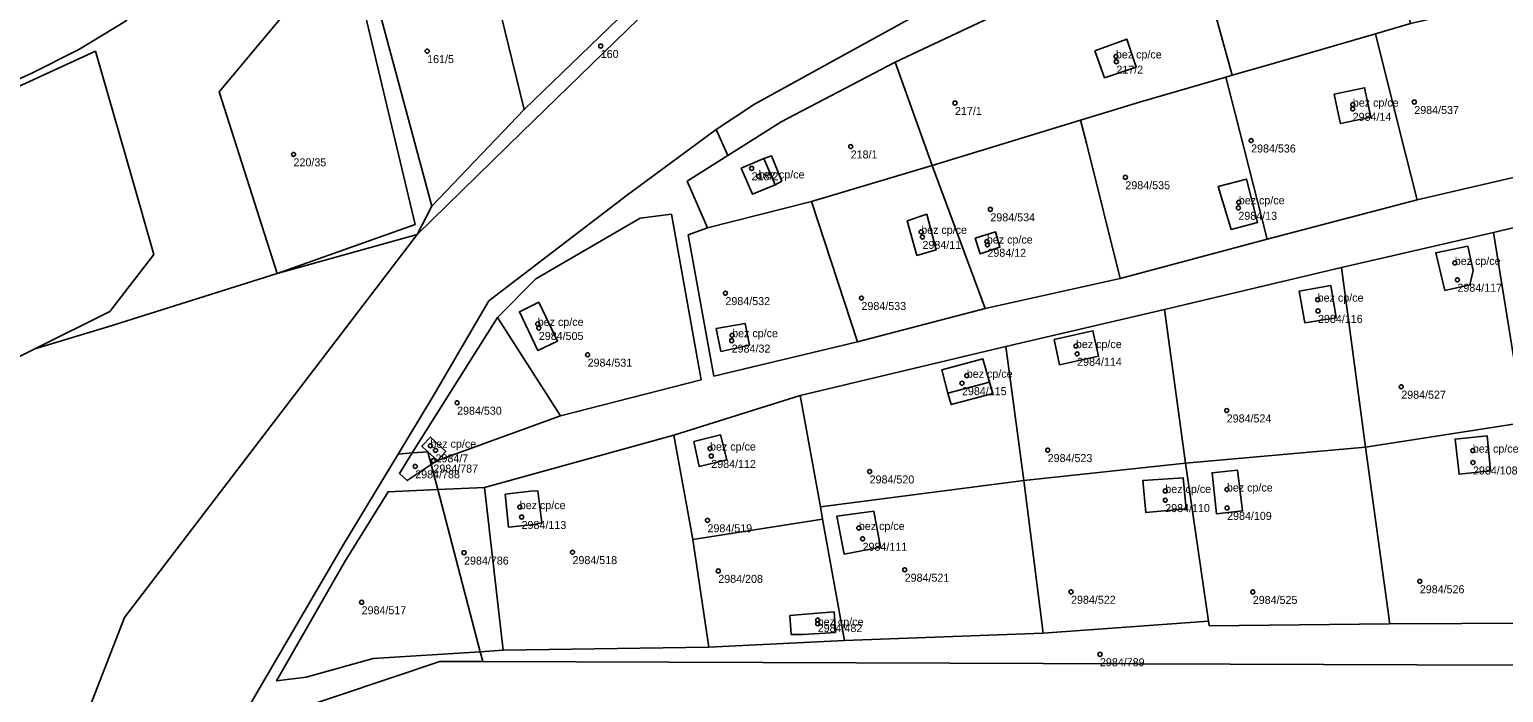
# Model space of a CAD drawing. Extents: x -878211 to -870363, y -1058464 to -1052522.
# Drawn here: x -874051.4 to -873867.2, y -1056092.9 to -1056010.1 of the extents above; entities that cross this region are included whole.
import ezdxf

# ---------------------------------------------------------------- set-up
doc = ezdxf.new("R2010")
doc.units = 0
for name, color, linetype in [('Vrstva 50', 7, 'Continuous'), ('Vrstva 51', 7, 'Continuous'), ('Vrstva 52', 7, 'Continuous')]:
    doc.layers.add(name, color=color, linetype=linetype)

msp = doc.modelspace()

# ---------------------------------------------------------------- linework, layer by layer
at = {"layer": 'Vrstva 50'}
for centre in [(-873980.05, -1056012.16994), (-874001.74, -1056012.80994), (-873915.68, -1056013.46994), (-873915.62, -1056014.12994), (-873935.78, -1056019.28994), (-873886.07, -1056019.48994), (-873878.39, -1056019.16994), (-873886.09, -1056020.01994), (-873948.82, -1056024.72994), (-873898.78, -1056023.97994), (-874018.44, -1056025.70994), (-873961.2, -1056027.44994), (-873960.31, -1056028.45994), (-873914.49, -1056028.56994), (-873900.37, -1056032.38994), (-873900.32, -1056031.68994), (-873931.36, -1056032.57994), (-873940.01, -1056035.38994), (-873939.85, -1056036.02994), (-873931.8, -1056036.59994), (-873931.73, -1056037.00994), (-873873.33, -1056039.26994), (-873873, -1056041.37994), (-873964.47, -1056043.04994), (-873947.47, -1056043.65994), (-873890.46, -1056043.85994), (-873890.42, -1056045.26994), (-873987.92, -1056046.88994), (-873987.79, -1056047.39994), (-873963.69, -1056048.97994), (-873963.63, -1056048.29994), (-873981.69, -1056050.73994), (-873920.68, -1056049.65994), (-873920.52, -1056050.62994), (-873934.91, -1056054.29994), (-873934.31, -1056053.35994), (-873880.02, -1056054.73994), (-873998, -1056056.73994), (-873901.83, -1056057.70994), (-874001.34, -1056062.10994), (-874000.7, -1056062.68994), (-873966.39, -1056062.45994), (-873966.24, -1056063.38994), (-873924.2, -1056062.65994), (-873871.08, -1056062.71994), (-874003.23, -1056064.68994), (-874000.96, -1056063.96994), (-873946.45, -1056065.32994), (-873871.06, -1056064.20994), (-873909.51, -1056068.90994), (-873909.5, -1056067.75994), (-873901.81, -1056067.57994), (-873990.17, -1056069.77994), (-873989.94, -1056071.01994), (-873901.78, -1056069.87994), (-873966.71, -1056071.42994), (-873947.8, -1056072.38994), (-873947.33, -1056073.73994), (-873997.13, -1056075.46994), (-873983.58, -1056075.40994), (-873965.36, -1056077.74994), (-873942.07, -1056077.60994), (-873921.28, -1056080.35994), (-873898.57, -1056080.37994), (-873877.7, -1056079.04994), (-874009.93, -1056081.66994), (-873952.94, -1056083.89994), (-873952.94, -1056084.34994), (-873917.67, -1056088.16994)]:
    msp.add_circle(centre, 0.25, dxfattribs=at)
at = {"layer": 'Vrstva 51'}
for points in [[(-874061.78, -1056020.31), (-874051.21, -1056015.58), (-874045.28, -1056012.6), (-874039.36, -1056009.01), (-874029.28, -1055999.36), (-874026.64, -1055995.1), (-874024.59, -1055990.32), (-874024.07, -1055987.79), (-874023.46, -1055978.22), (-874024.41, -1055972.01), (-874026.04, -1055967.55), (-874027.4, -1055965.3), (-874028.36, -1055963.96), (-874031.92, -1055959.69), (-874036.44, -1055955.98), (-874044.57, -1055950.98), (-874047.99, -1055949.47), (-874050.57, -1055948.5), (-874079.9, -1055941.21)], [(-873865.37, -1055954.75), (-873878.23, -1055960.39), (-873892.52, -1055966.18), (-873911.31, -1055974.31), (-873925.46, -1055980.46), (-873932.28, -1055983.42), (-873939.2, -1055986.41), (-873946.14, -1055989.65), (-873958.05, -1055994.81), (-873966.71, -1056000.36), (-873975.38, -1056008.83), (-873989.92, -1056022.91), (-874003.01, -1056035.73), (-874039.57, -1056083.57), (-874048.77, -1056107.25), (-874057.99, -1056135.83), (-874062.23, -1056148.73), (-874064.44, -1056172.46), (-874059.65, -1056228.47), (-874059.11, -1056233.23), (-874058.08, -1056239.54)], [(-874040.92, -1056237.64), (-874034.08, -1056235.73), (-874035.3, -1056231.92), (-874038.77, -1056221.03), (-874041.72, -1056201.74), (-874042.62, -1056175.62), (-874041.38, -1056163.05), (-874040.39, -1056153.05), (-874039.88, -1056147.87), (-874035.94, -1056133.05), (-874033.12, -1056122.42), (-874026.65, -1056099.18), (-874012.21, -1056074.45), (-874005.36, -1056063.14), (-874001, -1056055.93), (-873994.02, -1056044.02), (-873976.69, -1056030.75), (-873965.62, -1056022.6), (-873960.85, -1056019.45), (-873933.34, -1056004.26), (-873896.15, -1055987.86), (-873830.39, -1055958.21)], [(-873830.39, -1055958.21), (-873896.15, -1055987.86), (-873933.34, -1056004.26), (-873960.85, -1056019.45), (-873965.62, -1056022.6), (-873964.15, -1056025.83), (-873957.5, -1056021.62), (-873943.25, -1056014.2), (-873906.38, -1055996.82), (-873884.55, -1055987.56), (-873872.55, -1055982.17), (-873859.95, -1055976.8)], [(-874061.28, -1056021.1), (-874043.19, -1056012.81), (-874038.62, -1056028.71), (-874035.88, -1056038.23), (-874041.39, -1056045.32), (-874050.77, -1056050.02), (-874041.66, -1056047.24), (-874020.49, -1056040.6), (-874003.01, -1056035.73), (-874001.15, -1056032.18), (-874010.89, -1055995.93)], [(-874039.36, -1056009.01), (-874045.28, -1056012.6), (-874051.21, -1056015.58), (-874061.78, -1056020.31)], [(-873859.93, -1056027.19), (-873878.04, -1056031.39), (-873896.77, -1056036.31), (-873915.14, -1056041.21), (-873932.03, -1056044.96), (-873947.96, -1056049.12), (-873965.9, -1056053.41), (-873969.12, -1056035.77), (-873966.69, -1056034.9), (-873969.26, -1056029.06), (-873964.15, -1056025.83), (-873965.62, -1056022.6), (-873976.69, -1056030.75), (-873994.02, -1056044.02), (-874001, -1056055.93), (-874005.36, -1056063.14), (-874003.6, -1056063), (-873992.97, -1056046.1), (-873988.15, -1056041.27), (-873975.13, -1056033.66), (-873971.22, -1056033.18), (-873967.5, -1056053.87), (-873985.07, -1056058.37), (-874000.43, -1056063.95), (-874001.22, -1056064.47), (-874000.4, -1056067.59), (-873994.59, -1056067.33), (-873970.91, -1056060.77), (-873955.12, -1056055.84), (-873929.41, -1056049.7), (-873909.62, -1056045.07), (-873887.49, -1056039.84), (-873868.5, -1056035.48), (-873846.23, -1056030.16)], [(-873840.34, -1056089.55), (-873878.08, -1056089.5), (-873994.8, -1056089.08), (-874000.16, -1056089.06), (-874019.41, -1056095.51), (-874027.71, -1056108.65), (-874034.52, -1056132.5), (-874040.39, -1056153.05), (-874041.38, -1056163.05), (-874040.47, -1056163.31), (-874027.4, -1056124.02), (-874022.95, -1056110.18), (-874014.9, -1056098.66), (-874004.66, -1056094.51), (-873961.82, -1056094.39), (-873878.1, -1056095.5), (-873849.14, -1056094.93)]]:
    msp.add_lwpolyline(points, dxfattribs=at)
for points in [[(-873971.94, -1056003.04), (-873976.33, -1055986.86), (-873996.44, -1055992.14), (-873989.6, -1056020.11)], [(-873884.55, -1055987.56), (-873906.38, -1055996.82), (-873903.56, -1056007.06), (-873901.15, -1056015.82), (-873896.45, -1056014.46), (-873883.25, -1056010.63), (-873878.85, -1056009.35), (-873879.27, -1056007.63), (-873881.39, -1055998.99)], [(-873996.44, -1055992.14), (-874010.89, -1055995.93), (-874001.15, -1056032.18), (-873989.6, -1056020.11)], [(-873901.15, -1056015.82), (-873903.56, -1056007.06), (-873906.38, -1055996.82), (-873943.25, -1056014.2), (-873938.62, -1056027.09), (-873920.09, -1056021.43), (-873912.71, -1056019.18), (-873901.93, -1056016.05)], [(-874003.26, -1056034.48), (-874011.74, -1055998.72), (-874027.74, -1056017.87), (-874020.49, -1056040.6)], [(-874003.26, -1056034.48), (-874020.49, -1056040.6), (-874027.74, -1056017.87), (-874011.74, -1055998.72)], [(-873975.38, -1056008.83), (-873966.71, -1056000.36), (-873971.94, -1056003.04), (-873989.6, -1056020.11), (-874001.15, -1056032.18), (-874003.01, -1056035.73), (-873989.92, -1056022.91)], [(-873883.25, -1056010.63), (-873880.23, -1056022.67), (-873878.04, -1056031.39), (-873859.93, -1056027.19), (-873863.92, -1056005.93), (-873878.85, -1056009.35)], [(-873917.1, -1056016.13), (-873918.3, -1056012.77), (-873914.33, -1056011.3), (-873913.16, -1056014.81)], [(-873917.1, -1056016.13), (-873913.16, -1056014.81), (-873914.33, -1056011.3), (-873918.3, -1056012.77)], [(-873880.23, -1056022.67), (-873883.25, -1056010.63), (-873896.45, -1056014.46), (-873901.15, -1056015.82), (-873901.93, -1056016.05), (-873900.77, -1056020.61), (-873896.77, -1056036.31), (-873878.04, -1056031.39)], [(-874068.51, -1056024.22), (-874079.34, -1056028.88), (-874068.35, -1056058.84), (-874050.77, -1056050.02), (-874041.39, -1056045.32), (-874035.88, -1056038.23), (-874038.62, -1056028.71), (-874043.19, -1056012.81), (-874061.28, -1056021.1)], [(-873938.62, -1056027.09), (-873943.25, -1056014.2), (-873957.5, -1056021.62), (-873964.15, -1056025.83), (-873969.26, -1056029.06), (-873966.69, -1056034.9), (-873953.71, -1056031.61)], [(-873896.77, -1056036.31), (-873900.77, -1056020.61), (-873901.93, -1056016.05), (-873912.71, -1056019.18), (-873920.09, -1056021.43), (-873919.37, -1056024.32), (-873915.14, -1056041.21)], [(-873887.86, -1056020.78), (-873887.63, -1056021.85), (-873883.84, -1056021.06), (-873884.6, -1056017.39), (-873888.4, -1056018.2)], [(-873887.86, -1056020.78), (-873888.4, -1056018.2), (-873884.6, -1056017.39), (-873883.84, -1056021.06), (-873887.63, -1056021.85)], [(-873919.37, -1056024.32), (-873920.09, -1056021.43), (-873938.62, -1056027.09), (-873932.03, -1056044.96), (-873915.14, -1056041.21)], [(-873957.42, -1056029.06), (-873958.25, -1056029.51), (-873961.09, -1056030.69), (-873962.49, -1056027.44), (-873959.66, -1056026.22), (-873958.72, -1056025.88)], [(-873957.42, -1056029.06), (-873958.72, -1056025.88), (-873959.66, -1056026.22), (-873962.49, -1056027.44), (-873961.09, -1056030.69), (-873958.25, -1056029.51)], [(-873932.03, -1056044.96), (-873938.62, -1056027.09), (-873953.71, -1056031.61), (-873947.96, -1056049.12)], [(-873897.97, -1056034.22), (-873899.37, -1056028.79), (-873902.88, -1056029.7), (-873901.27, -1056035.08)], [(-873897.97, -1056034.22), (-873901.27, -1056035.08), (-873902.88, -1056029.7), (-873899.37, -1056028.79)], [(-873861.04, -1056058.94), (-873842.65, -1056057.61), (-873846.23, -1056030.16), (-873868.5, -1056035.48), (-873864.66, -1056059.2)], [(-873953.71, -1056031.61), (-873966.69, -1056034.9), (-873969.12, -1056035.77), (-873965.9, -1056053.41), (-873947.96, -1056049.12)], [(-873985.07, -1056058.37), (-873967.5, -1056053.87), (-873971.22, -1056033.18), (-873975.13, -1056033.66), (-873988.15, -1056041.27), (-873992.97, -1056046.1)], [(-873938.15, -1056037.61), (-873939.31, -1056033.18), (-873941.74, -1056033.99), (-873940.55, -1056038.33)], [(-873938.15, -1056037.61), (-873940.55, -1056038.33), (-873941.74, -1056033.99), (-873939.31, -1056033.18)], [(-874083.99, -1056066.24), (-874080.7, -1056077.88), (-874075.33, -1056096.89), (-874092.05, -1056109.34), (-874118.47, -1056117.14), (-874116.81, -1056122.76), (-874101.89, -1056134.11), (-874098.83, -1056136.48), (-874062.01, -1056135.86), (-874057.99, -1056135.83), (-874048.77, -1056107.25), (-874039.57, -1056083.57), (-874003.01, -1056035.73), (-874020.49, -1056040.6), (-874041.66, -1056047.24), (-874050.77, -1056050.02), (-874068.35, -1056058.84)], [(-873933.26, -1056036.18), (-873932.65, -1056038.12), (-873930.16, -1056037.29), (-873930.73, -1056035.39)], [(-873933.26, -1056036.18), (-873930.73, -1056035.39), (-873930.16, -1056037.29), (-873932.65, -1056038.12)], [(-873868.5, -1056035.48), (-873887.49, -1056039.84), (-873884.49, -1056062.27), (-873864.66, -1056059.2)], [(-873871.46, -1056042), (-873871.04, -1056040.2), (-873871.7, -1056037.17), (-873875.71, -1056038), (-873874.56, -1056042.71)], [(-873871.46, -1056042), (-873874.56, -1056042.71), (-873875.71, -1056038), (-873871.7, -1056037.17), (-873871.04, -1056040.2)], [(-873907, -1056064.3), (-873884.49, -1056062.27), (-873887.49, -1056039.84), (-873909.62, -1056045.07)], [(-873888.82, -1056042.1), (-873892.79, -1056042.8), (-873892.05, -1056046.75), (-873888.14, -1056046.12)], [(-873888.82, -1056042.1), (-873888.14, -1056046.12), (-873892.05, -1056046.75), (-873892.79, -1056042.8)], [(-873987.79, -1056044.18), (-873990.21, -1056045.38), (-873987.9, -1056050.21), (-873985.45, -1056049.03)], [(-873987.79, -1056044.18), (-873985.45, -1056049.03), (-873987.9, -1056050.21), (-873990.21, -1056045.38)], [(-873909.62, -1056045.07), (-873929.41, -1056049.7), (-873927.19, -1056066.46), (-873907, -1056064.3)], [(-874003.6, -1056063), (-874001.64, -1056062.85), (-874002.41, -1056062.16), (-874001.33, -1056061.02), (-873999.41, -1056062.83), (-874000.43, -1056063.95), (-873985.07, -1056058.37), (-873992.97, -1056046.1)], [(-873965.63, -1056047.46), (-873965.03, -1056050.32), (-873961.45, -1056049.53), (-873962.02, -1056046.82)], [(-873965.63, -1056047.46), (-873962.02, -1056046.82), (-873961.45, -1056049.53), (-873965.03, -1056050.32)], [(-873918.55, -1056047.75), (-873923.41, -1056048.85), (-873922.72, -1056051.99), (-873917.84, -1056050.9)], [(-873918.55, -1056047.75), (-873917.84, -1056050.9), (-873922.72, -1056051.99), (-873923.41, -1056048.85)], [(-873927.19, -1056066.46), (-873929.41, -1056049.7), (-873955.12, -1056055.84), (-873952.61, -1056069.75)], [(-873937.44, -1056052.61), (-873936.66, -1056055.54), (-873936.26, -1056056.97), (-873931.06, -1056055.59), (-873931.47, -1056054.18), (-873932.29, -1056051.25)], [(-873937.44, -1056052.61), (-873932.29, -1056051.25), (-873931.47, -1056054.18), (-873931.06, -1056055.59), (-873936.26, -1056056.97), (-873936.66, -1056055.54)], [(-873955.12, -1056055.84), (-873970.91, -1056060.77), (-873968.55, -1056073.84), (-873952.33, -1056071.3), (-873952.61, -1056069.75)], [(-873863.42, -1056084.29), (-873863.45, -1056083.69), (-873864.66, -1056059.2), (-873884.49, -1056062.27), (-873881.55, -1056083.76), (-873881.47, -1056084.35)], [(-873999.41, -1056062.83), (-874001.33, -1056061.02), (-874002.41, -1056062.16), (-874001.64, -1056062.85), (-874000.43, -1056063.95)], [(-873992.23, -1056087.66), (-873966.56, -1056087.27), (-873968.55, -1056073.84), (-873970.91, -1056060.77), (-873994.59, -1056067.33)], [(-873967.75, -1056064.71), (-873964.3, -1056063.86), (-873965.07, -1056060.76), (-873968.4, -1056061.59)], [(-873967.75, -1056064.71), (-873968.4, -1056061.59), (-873965.07, -1056060.76), (-873964.3, -1056063.86)], [(-873868.87, -1056065.26), (-873869.28, -1056060.88), (-873873.3, -1056061.27), (-873872.79, -1056065.66)], [(-873868.87, -1056065.26), (-873872.79, -1056065.66), (-873873.3, -1056061.27), (-873869.28, -1056060.88)], [(-874012.08, -1056076.67), (-874006.62, -1056067.86), (-874000.4, -1056067.59), (-874001.22, -1056064.47), (-874004.25, -1056066.47), (-874005.21, -1056065.57), (-874003.6, -1056063), (-874005.36, -1056063.14), (-874012.21, -1056074.45), (-874026.65, -1056099.18), (-874033.12, -1056122.42), (-874035.94, -1056133.05), (-874034.52, -1056132.5), (-874027.71, -1056108.65), (-874019.41, -1056095.51), (-874000.16, -1056089.06), (-873994.8, -1056089.08), (-873995.12, -1056087.84), (-874008.5, -1056088.69), (-874016.88, -1056091.03), (-874020.55, -1056091.49)], [(-874001.22, -1056064.47), (-874001.64, -1056062.85), (-874003.6, -1056063), (-874005.21, -1056065.57), (-874004.25, -1056066.47)], [(-874001.22, -1056064.47), (-874000.43, -1056063.95), (-874001.64, -1056062.85)], [(-873881.55, -1056083.76), (-873884.49, -1056062.27), (-873907, -1056064.3), (-873904.11, -1056084.01), (-873904.02, -1056084.6), (-873881.47, -1056084.35)], [(-873907, -1056064.3), (-873927.19, -1056066.46), (-873924.77, -1056085.52), (-873904.11, -1056084.01)], [(-873903.09, -1056070.63), (-873899.87, -1056070.25), (-873900.5, -1056065.14), (-873903.66, -1056065.49)], [(-873903.09, -1056070.63), (-873903.66, -1056065.49), (-873900.5, -1056065.14), (-873899.87, -1056070.25)], [(-873949.6, -1056086.44), (-873924.77, -1056085.52), (-873927.19, -1056066.46), (-873952.61, -1056069.75), (-873952.33, -1056071.3)], [(-873906.88, -1056069.99), (-873907.28, -1056066.1), (-873912.3, -1056066.44), (-873911.93, -1056070.45)], [(-873906.88, -1056069.99), (-873911.93, -1056070.45), (-873912.3, -1056066.44), (-873907.28, -1056066.1)], [(-874000.4, -1056067.59), (-874006.62, -1056067.86), (-874012.08, -1056076.67), (-874020.55, -1056091.49), (-874016.88, -1056091.03), (-874008.5, -1056088.69), (-873995.12, -1056087.84)], [(-873992.23, -1056087.66), (-873994.59, -1056067.33), (-874000.4, -1056067.59), (-873995.12, -1056087.84)], [(-873988.36, -1056071.96), (-873987.41, -1056071.73), (-873987.92, -1056067.76), (-873988.84, -1056067.77), (-873991.98, -1056068.16), (-873991.56, -1056072.29)], [(-873988.36, -1056071.96), (-873991.56, -1056072.29), (-873991.98, -1056068.16), (-873988.84, -1056067.77), (-873987.92, -1056067.76), (-873987.41, -1056071.73)], [(-873945.92, -1056070.3), (-873950.54, -1056070.92), (-873949.65, -1056075.65), (-873945.08, -1056074.79)], [(-873945.92, -1056070.3), (-873945.08, -1056074.79), (-873949.65, -1056075.65), (-873950.54, -1056070.92)], [(-873952.33, -1056071.3), (-873968.55, -1056073.84), (-873966.56, -1056087.27), (-873949.6, -1056086.44)], [(-873994.8, -1056089.08), (-873878.08, -1056089.5), (-873840.34, -1056089.55), (-873842.5, -1056082.5), (-873863.42, -1056084.29), (-873881.47, -1056084.35), (-873904.02, -1056084.6), (-873904.11, -1056084.01), (-873924.77, -1056085.52), (-873949.6, -1056086.44), (-873966.56, -1056087.27), (-873992.23, -1056087.66), (-873995.12, -1056087.84)], [(-873950.73, -1056085.43), (-873954.74, -1056085.68), (-873956.24, -1056085.71), (-873956.44, -1056083.32), (-873954.97, -1056083.2), (-873950.89, -1056082.86)], [(-873950.73, -1056085.43), (-873950.89, -1056082.86), (-873954.97, -1056083.2), (-873956.44, -1056083.32), (-873956.24, -1056085.71), (-873954.74, -1056085.68)]]:
    msp.add_lwpolyline(points, close=True, dxfattribs=at)
at = {"layer": 'Vrstva 52'}
for points in [[(-873918.3, -1056012.77), (-873917.1, -1056016.13), (-873913.16, -1056014.81), (-873914.33, -1056011.3)], [(-873887.63, -1056021.85), (-873883.84, -1056021.06), (-873884.6, -1056017.39), (-873888.4, -1056018.2), (-873887.86, -1056020.78)], [(-873962.49, -1056027.44), (-873961.09, -1056030.69), (-873958.25, -1056029.51), (-873959.66, -1056026.22)], [(-873899.37, -1056028.79), (-873902.88, -1056029.7), (-873901.27, -1056035.08), (-873897.97, -1056034.22)], [(-873939.31, -1056033.18), (-873941.74, -1056033.99), (-873940.55, -1056038.33), (-873938.15, -1056037.61)], [(-873933.26, -1056036.18), (-873932.65, -1056038.12), (-873930.16, -1056037.29), (-873930.73, -1056035.39)], [(-873871.7, -1056037.17), (-873875.71, -1056038), (-873874.56, -1056042.71), (-873871.46, -1056042), (-873871.04, -1056040.2)], [(-873892.79, -1056042.8), (-873892.05, -1056046.75), (-873888.14, -1056046.12), (-873888.82, -1056042.1)], [(-873990.21, -1056045.38), (-873987.9, -1056050.21), (-873985.45, -1056049.03), (-873987.79, -1056044.18)], [(-873965.63, -1056047.46), (-873965.03, -1056050.32), (-873961.45, -1056049.53), (-873962.02, -1056046.82)], [(-873923.41, -1056048.85), (-873922.72, -1056051.99), (-873917.84, -1056050.9), (-873918.55, -1056047.75)], [(-873937.44, -1056052.61), (-873936.66, -1056055.54), (-873931.47, -1056054.18), (-873932.29, -1056051.25)], [(-874001.33, -1056061.02), (-874002.41, -1056062.16), (-874001.64, -1056062.85), (-874000.43, -1056063.95), (-873999.41, -1056062.83)], [(-873968.4, -1056061.59), (-873967.75, -1056064.71), (-873964.3, -1056063.86), (-873965.07, -1056060.76)], [(-873873.3, -1056061.27), (-873872.79, -1056065.66), (-873868.87, -1056065.26), (-873869.28, -1056060.88)], [(-873900.5, -1056065.14), (-873903.66, -1056065.49), (-873903.09, -1056070.63), (-873899.87, -1056070.25)], [(-873907.28, -1056066.1), (-873912.3, -1056066.44), (-873911.93, -1056070.45), (-873906.88, -1056069.99)], [(-873988.84, -1056067.77), (-873991.98, -1056068.16), (-873991.56, -1056072.29), (-873988.36, -1056071.96), (-873987.41, -1056071.73), (-873987.92, -1056067.76)], [(-873950.54, -1056070.92), (-873949.65, -1056075.65), (-873945.08, -1056074.79), (-873945.92, -1056070.3)], [(-873954.97, -1056083.2), (-873956.44, -1056083.32), (-873956.24, -1056085.71), (-873954.74, -1056085.68), (-873950.73, -1056085.43), (-873950.89, -1056082.86)]]:
    msp.add_lwpolyline(points, close=True, dxfattribs=at)

# ---------------------------------------------------------------- texts
at = {"layer": 'Vrstva 50'}
for s, p in [('161/5', (-874001.74, -1056014.299)), ('160', (-873980.05, -1056013.659)), ('bez cp/ce', (-873915.68, -1056013.72)), ('217/2', (-873915.62, -1056015.619)), ('bez cp/ce', (-873886.07, -1056019.74)), ('217/1', (-873935.78, -1056020.779)), ('2984/14', (-873886.09, -1056021.509)), ('2984/537', (-873878.39, -1056020.659)), ('2984/536', (-873898.78, -1056025.469)), ('220/35', (-874018.44, -1056027.199)), ('218/1', (-873948.82, -1056026.219)), ('218/2', (-873961.2, -1056028.939)), ('bez cp/ce', (-873960.31, -1056028.71)), ('2984/535', (-873914.49, -1056030.059)), ('bez cp/ce', (-873900.32, -1056031.94)), ('2984/534', (-873931.36, -1056034.069)), ('2984/13', (-873900.37, -1056033.879)), ('bez cp/ce', (-873940.01, -1056035.639)), ('bez cp/ce', (-873931.8, -1056036.85)), ('2984/11', (-873939.85, -1056037.519)), ('2984/12', (-873931.73, -1056038.499)), ('bez cp/ce', (-873873.33, -1056039.52)), ('bez cp/ce', (-873890.46, -1056044.11)), ('2984/117', (-873873, -1056042.869)), ('2984/532', (-873964.47, -1056044.539)), ('2984/533', (-873947.47, -1056045.149)), ('bez cp/ce', (-873987.92, -1056047.139)), ('2984/116', (-873890.42, -1056046.759)), ('2984/505', (-873987.79, -1056048.889)), ('bez cp/ce', (-873963.63, -1056048.55)), ('bez cp/ce', (-873920.68, -1056049.909)), ('2984/32', (-873963.69, -1056050.469)), ('2984/531', (-873981.69, -1056052.229)), ('bez cp/ce', (-873934.31, -1056053.61)), ('2984/114', (-873920.52, -1056052.119)), ('2984/115', (-873934.91, -1056055.789)), ('2984/527', (-873880.02, -1056056.229)), ('2984/530', (-873998, -1056058.229)), ('2984/524', (-873901.83, -1056059.199)), ('bez cp/ce', (-874001.34, -1056062.36)), ('bez cp/ce', (-873966.39, -1056062.71)), ('2984/7', (-874000.7, -1056064.179)), ('2984/523', (-873924.2, -1056064.149)), ('bez cp/ce', (-873871.08, -1056062.97)), ('2984/788', (-874003.23, -1056066.179)), ('2984/787', (-874000.96, -1056065.459)), ('2984/112', (-873966.24, -1056064.879)), ('2984/108', (-873871.06, -1056065.699)), ('2984/520', (-873946.45, -1056066.819)), ('bez cp/ce', (-873909.5, -1056068.01)), ('bez cp/ce', (-873901.81, -1056067.83)), ('bez cp/ce', (-873990.17, -1056070.03)), ('2984/110', (-873909.51, -1056070.399)), ('2984/109', (-873901.78, -1056071.369)), ('2984/113', (-873989.94, -1056072.509)), ('2984/519', (-873966.71, -1056072.919)), ('bez cp/ce', (-873947.8, -1056072.639)), ('2984/111', (-873947.33, -1056075.229)), ('2984/786', (-873997.13, -1056076.959)), ('2984/518', (-873983.58, -1056076.899)), ('2984/208', (-873965.36, -1056079.239)), ('2984/521', (-873942.07, -1056079.099)), ('2984/526', (-873877.7, -1056080.539)), ('2984/522', (-873921.28, -1056081.849)), ('2984/525', (-873898.57, -1056081.869)), ('2984/517', (-874009.93, -1056083.159)), ('bez cp/ce', (-873952.94, -1056084.6)), ('2984/482', (-873952.94, -1056085.389)), ('2984/789', (-873917.67, -1056089.659))]:
    msp.add_text(s, height=0.999996, dxfattribs=at).set_placement(p)

doc.saveas('drawing.dxf')
